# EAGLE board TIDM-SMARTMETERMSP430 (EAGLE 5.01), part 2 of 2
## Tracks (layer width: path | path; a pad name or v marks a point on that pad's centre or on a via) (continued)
N$16 (continued)
  Top 0.406: R21.2 57.91,46.72 58.14,46.49 57.91,46.27 R20.1
N$17
  Top 0.813: 2.2,61.68 U$2.3 | U$2.2 2.2,61.68 | 2.2,61.68 2.26,61.73
N$19
  Top 0.406: R22.2 57.91,50.84 57.88,50.81 57.91,50.79 R21.1 57.87,48.54 57.63,48.78 56.87,48.78 56.09,49.55 54.59,49.55 54.55,49.52 | 54.55,49.52 54.33,49.29 | R23.1 54.55,49.52
N$20
  Top 0.406: C26.1 R43.1
N$21
  Top 0.254: 119.92,66.11 119.86,66.05 | U4.2 119.92,66.11 | 119.92,66.11 119.95,66.14
  Top 0.406: 119.95,66.14 R51.2
N$22
  Top 0.254: 109.52,69 109.55,69.02 Q3.B 109.66,69.39 109.44,69.61
  Top 0.406: R52.2 108.34,71.98 109.44,70.88 109.44,69.61
N$23  (via drill 0.6)
  Top 0.406: R119.1 27.15,43.19 v28.42,43.95 | ISO1.1 22.76,53.28 22.83,53.35 23.08,53.1 v25.62,53.1
  Bottom 0.406: v28.42,43.95 28.42,50.3 v25.62,53.1
N$26
  Top 0.254: R50.2 110.69,67.04 | 114.78,67.47 114.75,67.45 | 114.78,67.47 114.8,67.45 | 113,68.95 113.99,69.94 | 113.25,67.45 113.25,67.58 | 114.78,67.47 114.78,67.58 114.72,67.52 U4.6
  Top 0.406: U4.6 113.25,67.45 111.09,67.45 110.69,67.04 | RS-232.2 129.05,68.64 127.99,67.58 122.63,67.58 121.13,69.84 113.99,69.94 | 113,68.95 113,67.83 113.25,67.58
N$27
  Top 0.406: R4.1 R54.2
N$28
  Top 0.406: R54.1 R55.2
N$29
  Top 0.406: R57.2 R55.1 68.64,44.55 68.59,44.5 | 68.59,44.5 68.55,44.46 | R56.1 68.59,44.5
N$30
  Top 0.254: LED3.C 98.02,118.11 98.01,118.12 R3.2
N$31
  Top 0.61: 104.68,31.29 104.69,31.31 | 104.68,31.29 R29.1 104.53,31.29 104.52,31.28 104.47,31.33 103.5,31.33 102.33,32.5 102.33,40.4 101.32,41.41 100.05,41.41 R101.2 | L7.2 104.67,31.28 104.68,31.29
N$32
  Top 0.61: R26.1 89.78,30.8 89.57,30.59 89.57,28.94 | L5.2 89.57,28.94 | 89.57,28.94 89.61,28.94 89.4,29.15 88.51,29.15 87.19,29.98 87.19,41.57 86.58,42.18 85.31,42.18 R104.2
N$33
  Top 0.61: L15.2 133.6,31.07 133.75,31.23 133.69,31.29 R62.1 132.57,31.29 132.07,31.53 132.07,41.39 131.24,42.23 R103.2
N$34
  Top 0.61: R63.1 119.6,31.51 119.62,31.49 L14.2 | R63.1 119.36,31.45 | 119.2,31.64 119.39,31.45 R63.1 | R63.1 119.41,31.45 119.35,31.51 118.33,31.51 117.37,32.98 117.37,41.11 116.2,42.28 R102.2
N$35
  Top 0.61: L16.2 107.72,31.15 107.74,31.18 107.64,31.28 R64.1 108.8,31.29 109.01,31.51 109.01,33.87 110.1,34.96 110.1,40.04 112.34,42.28 R102.1 112.49,42.94 116.81,47.26 JP10.2
N$36
  Top 0.61: 122.35,28.26 122.32,28.29 L17.2 | 122.35,28.26 R65.1 123.48,31.32 123.92,31.76 123.92,34.3 124.68,35.06 124.68,39.38 127.73,42.43 128.49,42.43 128.57,42.35 R103.1 128.7,42.38 130.53,44.21 JP11.2 | 122.35,28.26 122.4,28.21
N$37
  Top 0.254: TP4.TP 115.54,156.98 115.51,157.01 RF1.13
N$38
  Top 0.254: R66.1 101.24,150.3 102.84,151.9 104.87,151.9 104.85,151.93 RF1.6
N$39
  Top 0.254: R67.1 101.67,152.01 102.84,153.17 105.13,153.17 105.1,153.2 RF1.8
N$40
  Top 0.254: R68.1 102.2,153.81 102.84,154.44 104.36,154.44 104.39,154.47 RF1.10
N$41
  Top 0.406: 81.05,25.77 77.16,25.77 76.55,26.38 76.55,27.06 76.68,27.19 76.53,27.33 L6.1
  Top 0.61: X4.1A 82.37,13.11 82.39,13.09 82.37,13.07 | D3.A 81.73,34.35 81.81,34.28 81.73,34.2 D4.C 81.56,32.98 81.5,33.03 80.49,33.03 79.73,32.27 79.73,28.71 81.05,27.39 81.05,25.77 81.1,25.71 | TVS1.A 81.1,25.71 | 81.1,25.71 81.17,25.64
  Top 0.813: 81.16,25.5 TVS1.A
  Top 1.27: X4.1 82.37,13.07 | X4.1A 82.37,24.29 81.16,25.5
N$42
  Top 0.254: R69.1 103.2,155.56 103.35,155.71 104.36,155.71 104.39,155.74 RF1.12
N$43
  Top 0.61: X7.1A 122.07,13.1 122.07,13.09 | D23.A 126.39,33.11 D24.C 125.32,32.9 124.94,32.52 124.94,26.53 125.01,26.45 126.21,26.45 126.23,26.43 126.27,26.46 TVS4.A 126.21,26.43 | 123.87,23.63 123.92,23.63 123.92,23.89 | 125.95,23.63 126.21,23.89 | 122.32,25.49 L17.1
  Top 0.813: 123.92,23.89 122.32,25.49
  Top 1.27: X7.1 122.07,13.09 | X7.1A 122.07,21.84 123.87,23.63 | 123.92,23.63 125.95,23.63 | 126.21,23.89 126.21,26.43
N$45
  Top 0.254: R70.1 102.99,157.34 103.35,156.98 104.62,156.98 104.64,157.01 RF1.14
N$46
  Top 0.254: R71.1 102.28,159.07 103.09,158.25 104.36,158.25 104.39,158.28 RF1.16
N$47
  Top 0.61: X6.2A 113.82,13.21 113.84,13.22 | TVS3.C 115.48,26.51 115.41,26.58 115.42,26.58 116.81,26.58 | 116.81,26.58 L14.1 | 115.03,32.6 D18.C | 115.03,32.6 D17.A | 115.03,32.6 116.3,32.63 116.81,31.99 116.81,26.58 | TVS3.C 115.46,26.12 115.31,25.97 115.41,25.87 | TVS3.C 115.13,25.77 115.26,25.64 115.29,25.67
  Top 1.27: X6.2 X6.2A | 113.84,13.22 113.84,20.38 115.26,21.81 115.26,25.64
N$48
  Top 0.61: 96.13,25.87 96.03,25.87 | 96.13,25.87 TVS2.A | 96.13,25.87 96.13,25.77 96.06,25.84 94.84,25.84 94.84,25.87 94.81,32.35 95.14,32.78 D8.C 96.39,32.98 D7.A | X5.1A 95.64,13.13 95.68,13.09 95.64,13.06
  Top 0.813: 96.13,25.77 96.24,25.67 95.64,25.07 | L8.1 92.43,25.92 92.48,25.87 94.84,25.87
  Top 1.27: X5.1 95.64,13.06 | X5.1A 95.64,25.07
N$49
  Top 0.61: X6.1A 108.8,13.33 108.78,13.35 | TVS3.A 111.38,25.9 111.2,25.72 111.45,25.47 | 111.38,26.21 111.48,26.3 | TVS3.A 111.38,26.21 | 109.93,26.11 111.28,26.11 111.38,26.21 | L16.1 109.77,26.11 109.93,26.11 | 111.48,32.55 D20.C | 111.48,32.55 D19.A | 111.48,32.55 110.15,32.5 109.93,32.07 109.93,26.11 | TVS3.A 111.38,25.95 111.17,25.74 | 111.48,26.12 111.53,26.17 | 111.48,26.12 TVS3.A | 111.27,25.92 111.48,26.12
  Top 1.27: X6.1 X6.1A | 108.8,13.33 108.8,17.97 111.27,20.43 111.27,25.92
N$50
  Top 0.254: R72.1 101.65,160.82 102.99,159.47 104.57,159.47 104.64,159.55 RF1.18
N$51
  Top 0.254: R73.1 101.26,162.65 103.07,160.85 104.74,160.85 RF1.20 104.85,160.74
N$52
  Top 0.254: 47.21,150.66 RF3.3 46.93,150.66 46.96,150.63 49.25,150.63 50.19,149.69 54.5,149.69 54.58,149.62 54.62,149.66 R108.2
N$53
  Top 0.254: RF1.15 TP13.TP
N$54
  Top 0.254: TP10.TP 115.31,159.55 115.29,159.52 115.26,159.55 RF1.17
N$55  (via drill 0.9)
  Top 0.813: U$2.8 14.39,56.46 14.45,56.4 v14.45,53.61
  Bottom 0.813: C59.1 11.15,6.62
  Bottom 1.27: v14.45,53.61 16.48,51.57 16.48,11.95 11.15,6.62
N$56
  Top 0.254: RF3.6 41.65,151.93 39.34,149.62 R77.1
N$57
  Top 0.254: RF3.8 40.89,153.2 39.09,151.4 38.07,151.4 37.99,151.47 R78.1
N$58
  Top 0.254: RF3.10 40.13,154.47 39.09,153.43 38.07,153.43 37.97,153.33 R79.1
N$59
  Top 0.254: RF2.18 74.62,159.55 74.65,159.52 74.58,159.46 R74.2
N$60
  Top 0.254: RF3.12 39.36,155.74 38.83,155.21 38.07,155.21 37.99,155.13 R80.1
N$61
  Top 0.254: R81.1 38.22,157.09 38.32,156.98 38.35,157.01 RF3.14
N$62
  Top 0.254: RF3.16 39.57,158.28 39.09,158.76 38.07,158.76 37.99,158.84 R82.1
N$63
  Top 0.254: RF3.18 40.1,159.55 39.06,160.59 38.12,160.59 38.07,160.54 37.97,160.64 R83.1
N$64
  Top 0.254: RF3.20 40.58,160.82 39.09,162.32 38.07,162.32 37.98,162.41 R84.1
N$65
  Top 0.254: R85.2 9.84,159.56 9.88,159.52 9.9,159.55 RF4.18
N$66
  Top 0.254: R87.1 18.77,158.25 18.74,158.28 RF4.15
N$67
  Top 0.254: RF3.11 52.78,155.74 TP25.TP
N$68
  Top 0.254: RF3.13 50.49,157.01 TP24.TP
N$69
  Top 0.254: TP27.TP 53.06,158.25 53.03,158.28 RF3.15
N$71
  Top 0.254: TP26.TP 50.54,159.55 50.52,159.52 50.49,159.55 RF3.17
N$72
  Top 0.61: 131.64,26.9 130.92,26.9 130.5,26.48 TVS4.C 130.3,26.4 130.4,26.3 | 131.64,26.9 L15.1 | 129.59,32.88 D22.C | 129.59,32.88 D21.A | 129.59,32.88 130.68,32.88 131.03,32.52 131.03,28.71 131.54,28.21 131.54,27.19 131.64,27.09 131.64,26.9
  Top 1.27: X7.2 X7.2A 127.09,22.34 128.09,23.33 129.76,23.33 130.4,23.96 130.4,26.3
N$73  (via drill 0.5)
  Top 0.254: Q1.B 20.21,44.63 v19.27,43.7 | R120.2 19.36,50.9 19.27,50.81 v19.27,49.03
  Top 0.406: Q1.B 20.61,44.53 20.54,44.46 20.54,43.19 19.53,42.18 19.53,40.4 | R112.1 17.15,39.8 17.75,40.4 19.53,40.4 | 19.53,40.4 D10.C
  Bottom 0.254: v19.27,43.7 v19.27,49.03
N$74
  Top 0.61: 42.73,125.83 42.64,125.74 | 42.73,125.83 R9.1 | 42.73,125.83 45.09,125.83 47.47,123.46 47.47,121.17 47.44,121.15 U$7.4
N$75
  Top 0.254: R10.2 72.87,150.38 73.12,150.63 73.88,150.63 73.91,150.66 RF2.4
N$76
  Top 0.254: R88.2 118.33,92.72 OK1.2
N$77  (via drill 0.5)
  Top 0.254: 116.05,58.43 116.07,58.41 C32.-
  Top 0.406: D16.A 119.63,58.15 119.6,58.18 C32.- | U4.5 116.43,68.72 116.81,68.34 116.81,63.51 v118.1,62.67 | v118.08,59.96 116.56,59.96 116.05,59.45 116.05,58.43
  Bottom 0.406: v118.08,59.96 v118.1,62.67
N$78  (via drill 0.6)
  Top 0.406: R45.1 124.6,69.52 126.46,71.39 RS-232.3 | v126.72,59.96 124.94,58.18 124.91,58.15 D16.C
  Bottom 0.254: v126.72,59.96 126.72,60.21 | 132.56,71.39 RS-232.3
  Bottom 0.406: 126.72,60.21 131.29,64.78 131.29,70.12 132.56,71.39
N$79  (via drill 0.6)
  Top 0.254: 119.86,67.58 119.92,67.52 U4.3 | 113.65,71.5 v113.76,71.39
  Top 0.406: v117.83,67.58 119.86,67.58 | Q3.C 113.65,71.5
  Bottom 0.406: v113.76,71.39 115.03,71.39 117.83,68.59 v117.83,67.58
N$80
  Top 0.254: OK1.4 126.72,99.83 SL1.1
N$81
  Top 0.406: SL1.2 121.89,98.31 OK1.3
N$82
  Top 0.254: RF1.5 111.96,151.93 112.75,151.14 R27.2 114.52,151.14
N$84
  Top 0.254: OK2.2 109.7,116.6 111.73,114.57 111.73,113.04 R89.2
N$85
  Top 0.254: R40.2 72.87,152.16 73.12,151.9 73.88,151.9 73.91,151.93 RF2.6
N$86
  Top 0.254: OK2.4 SL2.1
N$87
  Top 0.254: OK2.3 SL2.2
N$88
  Top 0.406: R111.2 R110.1
N$89
  Top 0.406: R41.1 79.76,153.21 79.73,153.17 79.7,153.2 RF2.7
N$91
  GND 0: 75.41,74.69 75.41,76.21 71.85,79.77 71.85,91.96 72.11,92.21 76.68,92.21 76.93,91.96 76.93,76.97 76.68,76.72 76.68,74.69
N$93  (via drill 0.5)
  Top 0.406: ISO1.2 22.3,50.54 | ISO1.2 24.63,50.54 26.89,48.27 26.89,46.49 26.73,46.66 C30.1 | D10.A 23.01,41.49 v22.32,42.18 | 22.58,50.56 22.32,50.81 v22.32,48.53 | 22.58,50.56 22.6,50.54 ISO1.2 | 22.58,50.56 22.66,50.64 22.66,51.24 21.05,52.84 18.26,52.84 17.66,52.25 R120.1 17.66,48.14 17.5,47.98 D25.A
  Bottom 0.406: v22.32,42.18 v22.32,48.53
N$94
  Top 0.406: R126.1 14.36,89.84 14.13,89.61 Q5.1 14.13,89.49 14.19,89.42 14.13,89.36 14.13,88.61 15.21,87.53 15.21,85.61 14.84,85.24 Q4.1
N$97
  Top 0.406: Q5.2 12.3,89.55 12.23,89.49 Q4.2
N$98
  Top 0.406: R36.1 22.32,101.1 22.32,99.83 22.58,99.58 23.59,99.58 24.21,98.96 24.21,97.91 Q9.1 | Q9.1 | Q8.1 Q9.1
N$99
  Top 0.406: R117.1 23.5,68.76 23.34,68.59 23.08,68.85 R118.2
N$100
  VCC 0: 75.41,74.69 75.41,76.21 71.85,79.77 71.85,91.96 72.11,92.21 76.68,92.21 76.93,91.96 76.93,76.97 76.68,76.72 76.68,74.69
N$103
  Top 0.406: 27.57,69.01 27.66,69.1 | 27.57,69.01 R116.1 | R117.2 27.4,68.85 27.57,69.01
N$104
  Top 0.254: RF1.3 111.7,150.66 113,149.36 R61.2 114.52,149.36
N$105
  Top 0.254: RF1.9 113.02,154.47 113.25,154.7 114.27,154.7 114.29,154.72 R60.2
N$106
  Top 0.254: R76.1 80.5,158.27 80.49,158.25 80.46,158.28 RF2.15
N$107
  Top 0.254: R75.1 82.81,160.76 82.75,160.82 RF2.19
N$108
  Top 0.254: R86.1 21.08,160.82 21.05,160.79 21.03,160.82 RF4.19
N$109
  Top 0.254: R107.2 48.79,154.75 48.48,154.44 46.45,154.44 46.48,154.47 RF3.9
N$110
  Top 0.254: R105.2 54.58,151.4 | R105.2 | R105.2 | R105.2 49.69,151.46 49.25,151.9 46.96,151.9 46.71,152.16 46.55,152.01 RF3.5
N$111
  Top 0.254: RF3.7 46.68,153.2 46.71,153.17 R106.2
N$113
  Top 0.406: R119.2 23.08,43.19 22.32,43.95 22.32,44.46 22.51,44.65 | 22.51,44.65 22.58,44.72 | Q1.E 22.51,44.65
N$115
  Top 0.61: R8.1 20.04,133.62 19.78,133.36 17.39,133.36 14.78,130.75 14.78,128.87 14.7,128.79 14.73,128.77 U$5.4
N$117
  Top 0.406: R121.2 26.89,59.96 26.81,59.87 Q2.E
N$118
  Top 0.406: R121.1 34.26,59.96 35.28,60.97 35.28,65.29 35.44,65.45 IS02.1 35.46,65.72 35.53,65.8
N$120
  Top 0.406: R123.2 27.4,71.39 27.32,71.3 Q6.E
N$121
  Top 0.406: 33.24,71.89 33.23,71.91 ISO3.1 33,71.91 32.99,71.89 29.18,71.89 28.76,71.47 R123.1
N$125
  Top 0.406: R111.1 21.05,37.86 20.8,37.6 20.54,37.86 R112.2
N$128  (via drill 0.5)
  Top 0.254: U$10.P$12 15.69,96.25 15.21,95.77 v15.21,95.26
  Top 0.406: 741G57.4 18.48,81.83 18,82.05 v16.99,82.05
  Bottom 0.254: v15.21,95.26 15.21,93.23 15.72,92.72
  Bottom 0.406: 15.72,92.72 18.77,92.72 19.53,91.96 19.51,87.93 16.99,86.63 v16.99,82.05
N$129
  Top 0.406: 10.13,82.05 10.38,81.8 10.38,80.53 10.34,80.58 BZ1.P$1 10.31,72.33 8.61,70.62 8.61,46.24 4.03,43.19 2.76,43.19 2.51,43.45 2.32,43.25 U$1.1 2.45,43.25 2.51,43.19 PLCV1.1 | 10.13,82.05 8.95,83.24 R33.2 8.86,84.59 | Q4.3 11.01,82.94 10.13,82.05
N$130
  Top 0.406: R114.2 R113.1
N$131
  Top 0.406: Q9.2 22.31,98.07 22.32,98.06 22.31,98.05 Q8.2
N$132  (via drill 0.5)
  Top 0.254: R47.1 110.56,73.06 110.84,72.78
  Top 0.406: 110.84,72.78 112.9,72.81 U3.8 115.92,72.78 117.06,73.93 117.06,80.02 J3.1 | R51.1 124.85,64.44 v125.95,65.54
  Bottom 0.406: J3.1 124.94,82.56 125.95,81.55 v125.95,65.54
N$139
  Top 0.406: Q11.1 35.51,99.57 35.53,99.58 35.51,99.6 Q10.1 35.51,101.63 34.21,102.63 20.31,102.63 19.27,101.87 19.27,100.6 19.36,100.68 R37.1
N$140
  Top 0.406: Q10.2 33.61,99.44 33.5,99.33 33.61,99.21 Q11.2
N$143
  Top 0.406: R115.2 R114.1
N$144  (via drill 0.5)
  Top 0.406: 21.81,59.7 21.64,59.87 Q2.B 21.63,58.75 21.05,58.18 18.42,58.18 18.17,57.92 18.17,57 18.26,56.91 | v24.35,65.8 D11.C | 18.26,56.91 R115.1 | v17.75,54.37 17.75,56.4 18.26,56.91 | v34.26,70.12 34.31,70.12 35.12,69.3 35.12,68.19 35.02,68.08 R122.2
  Bottom 0.406: v17.75,54.37 16.73,55.38 16.73,64.02 18.51,65.8 v24.35,65.8 24.35,67.83 26.13,69.61 33.75,69.61 v34.26,70.12
N$145  (via drill 0.5)
  Top 0.406: Q6.B 22.13,71.2 21.89,70.96 20.37,70.96 19.02,69.61 19.02,68.59 | 19.02,68.59 18.93,68.68 R118.1 | D9.C 28.42,77.99 v30.2,79.26 | 19.02,68.59 19.02,68.34 18.77,68.34 v17.5,67.07
  Top 0.61: D9.C 29.69,77.99 30.7,76.97 R124.2 30.7,75.2
  Bottom 0.406: v30.2,79.26 25.62,79.26 19.02,72.66 19.02,68.59 v17.5,67.07
N$202
  Top 0.406: R28.1 76.46,31.8 76.42,31.76 76.53,31.65 L6.2
  Top 0.61: R28.1 77.78,31.8 79.07,33.34 79.07,38.6 81.63,40.91 81.61,40.93 R104.1 82.37,41.01 85.06,43.7 87.85,43.7 90.65,46.49 JP3.2
N$229
  Top 0.61: L8.2 92.43,31 92.45,31.03 R31.1 93.48,31.29 93.95,31.76 93.95,34.56 94.89,35.5 94.89,39.31 97.35,41.01 R101.1 | JP4.2 103.09,45.99 101.06,43.95 98.57,43.95 97.4,42.79 R101.1 | R101.1 97.38,40.98
OPTO  (via drill 0.5)
  Top 0.254: R88.1 118.33,88.66 118.59,88.4 JP5.1 123.34,85.94 v123.34,79.64 | v79.98,67.32 79.98,61.99 80.49,61.48 v81.22,61.48 | MSP430F47187.68 74.8,73.52 v76.17,72.15
  Bottom 0.254: 123.41,79.51 123.34,79.59 v123.34,79.64 | v76.17,72.15 76.17,71.89 79.98,68.08 v79.98,67.32 | 120.37,59.96 117.57,57.16 104.36,57.16 100.05,61.48 v81.22,61.48
  Bottom 0.406: 120.37,59.96 120.37,76.47 123.41,79.51
OPTO2  (via drill 0.5)
  Top 0.254: MSP430F47187.46 84.15,71.6 83.69,70.63 83.79,67.32 83.68,67.22 v83.68,67.16 | JP6.1 117.57,113.04 R89.1 | R89.1 113.25,113.04 | R89.1 113.7,112.98 113.51,112.79 113.74,112.56 113.74,104.38 v113.25,103.9
  Bottom 0.254: 121.61,108.98 JP6.1 121.64,108.72 | v83.68,67.16 83.7,67.16 83.79,67.07 83.84,67.12 85.42,67.12 88.13,64.43 101.21,64.43 102.33,65.54 102.33,83.32 104.36,85.36 109.24,85.36 110,86.11 110,86.12 113.76,89.93 113.76,103.39 v113.25,103.9
P1+
  Top 0.406: X1.2A
  Top 0.813: L1.1 44.66,23.9 44.93,23.63 44.66,23.36
  Top 1.27: X1.2 X1.2A 44.66,23.36
P1+1  (via drill 0.9)
  Top 0.406: R110.2 26.98,37.77 27.15,37.6 26.89,37.35
  Top 0.813: R12.2 38.39,33.22 44.42,27.19 44.33,27.1 R17.2 44.18,26.95 | 42.9,23.89 42.96,23.95 L1.2 | U$6.18 7.08,122.69 1.49,117.11 1.49,81.8 v2.26,81.04 | v6.57,47.76 v6.57,59.19 | v5.05,22.36 18.77,22.36 25.19,28.79 C58.2 25.19,33.36 26.89,35.06 26.89,37.6 26.98,37.69 R110.2 | U$4.L 28.42,37.6 27.15,37.6
  Top 1.27: 44.18,26.95 42.9,25.67 42.9,23.89
  Bottom 0.61: 25.12,28.71 25.19,28.79 C58.2 | 27.15,26.68 27.4,26.68
  Bottom 0.813: R17.2 44.08,27.36 43.4,26.68 | v2.26,81.04 2.26,69.1 0.99,67.83 0.99,64.78 v6.57,59.19
  Bottom 1.27: 27.4,26.68 43.4,26.68 | 25.12,28.71 27.15,26.68 | v6.57,47.76 6.57,41.92 5.05,40.4 v5.05,22.36
P1-
  Top 0.813: X1.1A 39.64,13.01 39.59,12.97 39.64,12.92 | 38.58,23.63 38.59,23.65 L2.1
  Top 1.27: X1.1 39.64,12.92 | X1.1A 39.64,21.56 38.58,22.62 38.58,23.63
P1-1  (via drill 0.9)
  Top 0.406: JP1.2 32.25,44.74 32.23,44.72 32,44.95 | 38.3,44.95 38.27,44.92 R16.2 | JP1.2 38.3,44.95 | 38.3,44.95 38.32,44.97 | JP1.2 32.46,44.95 32.48,44.97 34.51,42.94 34.51,40.14 32.22,37.85 32.23,37.6 R18.2 | 14.3,76.61 14.19,76.72 | U$3.5 14.3,76.61 | 14.3,76.61 14.45,76.47 | C50.2 23.08,63.51 22.58,63 Q2.C | Q2.C 22.58,61.99 | C53.2 26.04,74.52 26.13,74.43 26.13,73.93 25.71,73.5 Q6.C 22.91,73.5 22.83,73.42 21.81,73.42 20.37,71.97 D27.C 19.02,71.89 18,71.89 17.5,72.4 16.73,72.4 | Q2.C 22.41,62.07 22.32,61.99 20.04,61.99 18.51,60.46 D26.C 16.91,59.78 16.73,59.96 16.73,63.51 16.23,64.02 14.45,64.02 14.39,64.08 U$2.5 | 32,44.95 31.97,44.97 26.13,44.97 25.03,46.07 C30.2 24.86,46.75 24.78,46.83 Q1.C 18.85,46.83 17.5,45.48 D25.C 17.5,44.46 17.37,44.59 16.49,44.59 16.09,45.01 16.09,50.7 15.97,50.81 14.19,50.81 | JP1.2 32,44.95 | R46.2 3.53,106.18 4.54,105.17 7.08,105.17 U$6.1
  Top 0.61: U$2.5 14.51,64.08 14.7,64.27 14.7,66.05 16.73,68.08 16.73,72.4 16.73,75.96 16.48,76.21 14.45,76.21 14.39,76.27 U$3.5
  Top 0.813: 33.88,31.38 32.2,33.06 32.23,35.57 R18.2 | 33.88,31.38 34.02,31.24 | 33.88,31.38 34.01,31.51 34.02,31.5 R17.1 34.02,25.65 35.53,24.14 36.8,24.14 36.88,24.07 L2.2 36.89,23.98 36.8,23.89 | 14.19,76.72 14.19,78.24 v13.18,79.26 | U$2.5 14.25,64.08 14.19,64.02 11.4,64.02 10.64,63.26 10.64,51.32 11.15,50.81 14.19,50.81 14.25,50.87 U$1.5
  Top 1.27: v12.42,14.49 34.51,14.49 36.8,16.78 36.8,23.89
  Bottom 0.813: 6.96,38.99 U$4.N | v13.18,79.26 9.62,79.26 7.84,81.04 7.84,104.66 U$6.1
  Bottom 1.27: v12.42,14.49 9.37,14.49 7.84,16.01 7.84,38.11 6.96,38.99
P1.5  (via drill 0.5)
  Top 0.254: v57.63,73.67 v55.6,73.67 | v68.1,68.5 68.2,68.5 68.3,68.6 MSP430F47187.86
  Top 0.406: PLC_GPIO.1 46.45,91.2 v47.98,89.93
  Bottom 0.254: v55.6,73.67 55.6,80.78 48.99,87.39 | v68.1,68.5 61.25,68.49 60.42,67.58 57.88,67.58 57.12,68.34 57.12,73.16 v57.63,73.67 | 48.99,87.39 48.97,87.41 | v47.98,89.93 47.98,88.4 48.99,87.39
P2+
  Top 0.813: X2.2A 58.54,13.07 58.64,12.97 58.54,12.86
  Top 1.27: X2.2 58.54,12.86 | L3.1 57.66,24.36 58.54,23.48 X2.2A
P2+1  (via drill 0.7, 0.9)
  Top 0.406: R24.2 55.79,33.48 | 55.85,33.29 55.8,33.24 R24.2 | R24.2 55.79,33.22
  Top 0.61: R113.2 28.51,48.18 v29.69,47
  Top 0.813: R19.2 57.96,35.65 55.79,33.48 | 33.24,17.79 C60.2 | 56.06,33.24 56.1,33.29 | R24.2 56.06,33.24 | L3.2 55.96,33.15 56.06,33.24
  Top 1.27: v30.45,29.48 30.45,20.59 33.24,17.79
  Bottom 0.813: 55.8,33.24 55.6,33.03 | C60.2 33.24,17.79 | v30.45,29.48 30.45,31.25 27.91,33.79 27.66,39.13 29.69,42.18 29.69,46.49 29.94,46.75 v29.69,47 | 55.85,33.29 55.8,33.24 | 55.8,33.24 R24.2
  Bottom 1.27: C60.2 52.8,17.79 55.85,20.84 55.85,33.29
P2-
  Top 0.406: X2.1A 53.52,13.01 53.56,12.97 53.52,12.92 | 49.5,24.14 49.41,24.23 | 49.5,23.89 49.46,23.93
  Top 0.813: 49.46,24.1 49.5,24.14
  Top 1.27: X2.1 53.52,12.92 | 49.41,24.23 L4.1 | X2.1A 53.52,19.11 49.5,23.13 49.5,23.89 | 49.46,23.93 49.46,24.1
P2-1
  Top 0.406: 51.02,42.18 51.05,42.2 R25.2 | JP2.2 49.22,49.52 49.25,49.54 49.27,49.52 51.79,49.52 | 51.79,49.52 R23.2 | 51.79,49.52 51.79,49.54 51.28,49.03 51.28,42.68 51.16,42.57 R25.2 | 45.63,36.78 R24.1 45.63,36.4 | 51.28,42.18 51.25,42.2 R25.2
  Top 0.813: 45.63,36.78 51.28,40.14 51.28,42.18 | L4.2 51.11,30.91 45.63,36.4
P2.0  (via drill 0.5)
  Top 0.254: MSP430F47187.83 72.38,70.1 74.39,68.08 75.41,68.08 75.46,68.13 v75.59,68.13
  Bottom 0.254: v75.59,68.13 75.61,68.13 75.66,68.08 74.65,67.07 62.45,67.07 60.68,65.29 57.88,65.29 56.61,66.56 56.61,77.99 61.18,82.56 63.98,82.56 65.5,84.09 65.5,88.91 66.52,89.93 66.52,113.04 63.72,115.84 63.72,123.96 64.99,125.23 RF2_FIFO.3
P2.6  (via drill 0.5)
  Top 0.254: MSP430F47187.77 70.4,73.1 70.58,72.91 70.58,72.4 70.84,72.15 72.36,72.15 72.54,72.33 72.54,74 72.36,74.18 70.84,74.18 70.58,74.43 70.58,75.2 69.36,76.42 v69.16,76.42 | v82.27,145.81 82.77,145.3 94.97,145.3 99.28,141.24 100.05,140.47 130.53,140.47 RF1_FIFO.3 | v69.82,147.33 70.33,147.33 74.14,143.52 79.22,143.52 82.01,140.73 v81.76,140.73
  Bottom 0.254: v69.16,76.42 67.53,78.24 67.53,87.9 68.52,88.91 68.55,102.07 68.55,102.53 70.89,105.12 70.89,146.77 v69.82,147.33 | v82.27,145.81 82.27,141.24 v81.76,140.73
P2.7  (via drill 0.5)
  Top 0.254: MSP430F47187.76 71.17,73.6 v71.62,73.01 | PLC_GPIO.3 48.99,96.79 52.55,93.23 v52.8,93.23 | v64.74,80.28 v64.74,93.23
  Bottom 0.254: v71.62,73.01 63.88,73.01 63.47,73.42 63.47,79.01 v64.74,80.28 | v64.74,93.23 v52.8,93.23
P3+
  Top 0.406: 73.53,13.37 73.63,13.47
  Top 1.27: X3.2 X3.2A 73.53,13.37 | 73.63,13.47 73.63,19.65 70.89,22.39 70.89,24.6 70.84,24.65 70.87,24.69 L12.1
P3+1  (via drill 0.7)
  Top 0.406: 69.24,28.13 R59.2 69.24,28.03 69.31,27.95 69.17,27.81
  Top 0.61: R116.2 29.94,68.85 30.45,68.34 v30.45,65.54
  Top 0.813: R4.2 71.34,30.24 69.24,28.13 | 69.17,27.81 L12.2
  Bottom 0.813: 69.24,28.03 R59.2 | v30.45,65.54 30.2,65.8 29.94,65.54 | 33.24,6.87 C59.2 33.32,6.79
  Bottom 1.27: 69.24,28.03 70.84,26.43 70.84,6.62 69.31,5.09 35.02,5.09 33.32,6.79 | 29.94,65.54 27.91,65.54 24.1,61.73 24.1,51.57 26.39,49.29 26.39,35.83 23.08,32.52 23.08,17.03 33.24,6.87
P3-
  Top 0.406: X3.1A 68.51,13.01 68.55,12.97 68.51,12.92 | L13.1 64.25,24.66 64.23,24.65 64.44,24.44 | 64.23,24.4 64.25,24.41
  Top 1.27: X3.1 68.51,12.92 | X3.1A 68.51,19.11 64.23,23.38 64.23,24.4 | 64.25,24.41 L13.1
P3-1
  Top 0.406: 66.01,24.9 65.95,24.84 L13.2 | R56.2 65.37,44.59 63.47,42.68 63.37,42.79 JP9.2 63.57,42.84 65.5,40.91 65.5,38.37 64.91,37.77 R58.2 64.91,35.91 64.99,35.83 | 61.03,31.4 61.33,31.4
  Top 0.813: 61.33,31.4 64.74,34.81 64.74,35.57 64.99,35.83
  Top 1.27: R59.1 61.03,31.4 66.01,26.43 66.01,24.9
P4.0  (via drill 0.5)
  Top 0.254: 81.78,75.3 81.8,75.31 MSP430F47187.54 81.8,74.58 79.98,72.79 79.98,72.54 79.98,68.59 80.34,68.24 81.66,68.24 82.01,68.59 | 82.01,68.59 | 82.01,68.59 v81.93,68.59
  Bottom 0.254: v81.93,68.59 82.01,68.59 82.52,68.08 85.31,68.08 88.39,64.99 100.97,64.99 101.82,65.86 101.82,83.58 104.11,85.86 109,85.86 109.38,86.25 109.39,86.25 113.25,90.11 113.25,101.61 111.98,102.88 111.98,123.71 116.43,128.16 RF1_GPIO.1
P4.4  (via drill 0.5)
  Top 0.254: MSP430F47187.50 85.75,73.6 86.84,74.43 86.84,78.75 v87.09,79.26 | v88.11,115.84 83.79,115.84 78.46,121.17 v73.88,121.17 | 6.32,136.66 6.5,136.84 RF2_GPIO.3 6.57,136.92 10.89,141.24 v73.88,141.24
  Bottom 0.254: v87.09,79.26 88.36,79.26 92.17,82.82 92.17,87.13 94.22,89.17 94.22,91.21 87.09,98.31 87.08,114.82 | 87.08,114.82 v88.11,115.84 87.09,114.82 87.08,114.82 | v73.88,141.24 v73.88,121.17 | RF2_GPIO.3 6.57,136.66
P5.0  (via drill 0.5)
  Top 0.254: MSP430F47187.55 81.3,76.26 83.28,78.24 v84.3,78.24 | RF1_GPIO.3 118.97,129.43 119.1,129.3 115.29,125.49 v100.55,125.49
  Bottom 0.254: v84.3,78.24 90.9,78.24 92.93,80.28 92.93,86.63 94.7,88.4 94.71,105.17 89.38,110.5 89.38,114.57 v100.55,125.49
P5.6  (via drill 0.5)
  Top 0.254: MSP430F47187.61 78.3,76.56 78.71,76.97 78.71,78.5 v79.22,79.01 | RF2_FIFO.1 62.45,125.23 63.72,126.5 v80.74,126.5
  Bottom 0.254: v79.22,79.01 79.22,87.13 76.68,89.67 76.68,92.72 79.73,95.77 79.73,109.23 77.95,111.01 77.95,114.06 79.73,115.84 79.73,125.49 v80.74,126.5
P5.7  (via drill 0.5)
  Top 0.254: MSP430F47187.62 77.8,67.47 v78.96,66.31
  Bottom 0.254: v78.96,66.31 85.31,66.31 85.33,66.32 87.88,63.82 101.37,63.82 102.84,65.29 102.84,83.07 104.62,84.85 109.44,84.85 114.27,89.67 114.27,111.77 116.81,114.31 130.27,114.31 132.05,116.09 RF1_FIFO.1
PC_GND  (via drill 0.5)
  Top 0.254: 123.16,76.21 D14.A | 132.63,76.9 132.66,76.87 RS-232.5 | 112.64,58.13 112.69,58.18 | 112.64,58.13 112.64,58.43 112.49,58.43 112.75,58.18 C32.+ | 112.64,58.13 112.62,58.1 | C31.- 112.49,61.73 112.64,61.89
  Top 0.406: 123.16,76.21 122.91,75.96 121.89,75.96 121.25,75.32 U3.3 118.46,75.32 118.08,75.7 v118.08,77.74 | D14.A 124.35,76.39 | v113.25,63.77 112.64,62.9 112.64,61.89 | 112.64,58.43 C31.-
  Top 0.61: 124.35,76.39 125.95,77.99 131.54,77.99 132.63,76.9 | RS-232.5 133.07,77.23
  Top 0.813: 131.54,77.99 131.29,78.24
  Top 1.27: 131.29,78.24 RS-232.G1
  Bottom 0.254: 118.59,77.74 v118.08,77.74
  Bottom 0.406: v113.25,63.77 118.59,63.77 119.35,64.27 119.35,76.97 118.59,77.74
PC_VCC
  Top 0.254: 132.81,74.18 132.76,74.13 RS-232.4 | 123.41,61.73 123.39,61.76 D15.A
  Top 0.406: 132.81,74.18 134.34,72.66 134.34,64.53 132.3,62.5 125.19,62.5 124.43,61.73 122.91,61.73 122.93,61.76 D15.A
PIN8
  Top 0.254: R50.1 110.69,65.06 110.84,64.91 | 119.6,61.73 119.63,61.76 D15.C | 114.78,65.04 114.72,64.98 U4.8
  Top 0.406: 110.84,64.91 U4.8 | 119.6,61.73 C31.+ 115.89,62.9 114.78,64.02 114.78,65.04
PLC_EN  (via drill 0.5)
  Top 0.254: JP7.2 JP7.4 JP7.6
  Top 0.406: U$14.9 49.93,99.76 v50.01,99.58
  Bottom 0.254: JP7.6 53.56,118.12 53.06,117.61 51.02,117.61 50.01,118.63 40.61,118.63 39.85,117.87 39.85,115.07 42.13,112.79 42.13,107.71 41.12,106.69 41.12,101.1 42.64,99.58 45.18,99.58 45.44,99.33 45.44,99.58
  Bottom 0.406: 45.18,99.58 45.44,99.58 v50.01,99.58
PLC_GPIO1
  Top 0.406: U$14.17 51.61,104.84 50.52,105.93 47.72,105.93 PLC_GPIO.2
PLC_GPIO2  (via drill 0.5)
  Top 0.406: U$14.30 59.99,112.46 v60.17,112.28
  Bottom 0.406: PLC_GPIO.4 57.63,104.66 60.17,107.2 v60.17,112.28
PLC_RESET  (via drill 0.5)
  Top 0.254: R109.1 49.08,112.45 49.25,112.28 49.42,112.46 U$14.29
  Top 0.406: 49.58,112.46 49.5,112.53 R109.1 49.08,112.7 48.99,112.79 v48.99,114.82
  Bottom 0.406: S4.1 58.14,119.9 55.09,116.85 50.26,116.85 48.99,115.58 v48.99,114.82
PLC_RX  (via drill 0.5)
  Top 0.254: U$14.12 62.28,101.03 v62.35,100.85 | v78.46,107.45 78.46,117.87 76.17,120.15 68.55,120.15 67.03,121.68 65.25,121.68 PLC_UART.4 | v78.71,96.53 78.71,95.26 81.5,92.47 113.76,92.47 v115.29,93.99 | v64.99,100.85 65.25,100.85 67.53,103.14 v67.53,106.18
  Top 0.406: U$8.3 39.66,136.09 v40.1,135.65 | v56.61,123.2 59.41,123.2 59.91,122.69 63.72,122.69 PLC_UART.4
  Bottom 0.254: PLC_UART.4 66.26,121.42 67.79,119.9 67.79,106.69 v67.53,106.18 | v62.35,100.85 v64.99,100.85 | v78.46,107.45 78.46,96.79 v78.71,96.53 | 109.95,84.09 114.78,88.91 114.78,93.48 v115.29,93.99
  Bottom 0.406: v40.1,135.65 40.1,129.81 46.71,123.2 v56.61,123.2 | JP13.2 106.9,62.24 108.68,64.02 108.68,82.82 109.95,84.09
PLC_TX  (via drill 0.5)
  Top 0.254: U$14.11 55.52,101.03 56.1,101.61 v56.1,115.84 | v115.67,91.71 81.5,91.71 v77.69,95.52 | v77.44,106.18 77.44,117.61 76.17,118.88 68.55,118.88 67.28,120.15 63.47,120.15 62.45,121.17
  Top 0.406: U$9.3 51.85,137.11 54.07,134.89 | 54.07,134.89 54.33,134.63 | PLC_UART.2 62.45,121.17 56.61,121.17 55.09,122.69 55.09,133.87 54.07,134.89 | v110.21,79.77 JP12.2
  Bottom 0.254: PLC_UART.2 61.69,121.42 v56.1,115.84 | 110.46,83.32 115.64,88.63 v115.67,91.71 | v77.69,95.52 77.69,105.93 v77.44,106.18
  Bottom 0.406: 110.46,83.32 110.46,80.02 v110.21,79.77
R33
  Top 0.254: C11.+ 88.11,80.53 87.07,81.52 81.86,81.52 80.49,80.1 78.53,80.15 78.2,79.46 78.2,77.23 77.3,76.32 MSP430F47187.63
RESETCC_A  (via drill 0.5)
  Top 0.254: MSP430F47187.47 87.55,72.1 89.38,73.93 89.38,80.02 87.35,82.05 83.03,82.05 v82.68,82.59 | R76.2 84.46,156.57 v84.55,156.48 | v117.83,150.63 117.83,150.38 117.06,151.14 R27.1
  Bottom 0.254: 83.28,126 86.58,129.3 86.58,154.44 v84.55,156.48 90.39,162.32 99.79,162.32 111.48,150.63 v117.83,150.63 | 83.28,126 82.52,125.23 | v82.68,82.59 82.24,82.59 81.53,83.3 81.53,89.37 81.5,111.43 81.5,111.77 81.76,112.03 81.76,124.47 83.28,126
RESETCC_B  (via drill 0.5)
  Top 0.254: v81.44,72.26 81.44,72.34 82.2,73.1 MSP430F47187.49 | R105.1 64.16,151.47 v64.23,151.4
  Top 0.406: R87.2 20.76,156.44 24.35,160.03 24.35,164.1 26.64,166.38 60.68,166.38 64.23,162.83 v64.23,151.4
  Bottom 0.254: v81.44,72.26 81.39,72.26 79.22,74.43 69.06,74.43 66.52,76.97 66.52,88.4 67.51,89.4 67.51,103.03 69.9,105.45 69.87,143.47 64.23,149.11 v64.23,151.4 64.49,151.14
RF1_GPIO1  (via drill 0.5)
  Top 0.254: R75.2 82.99,159.06 83.03,159.02 83.79,159.02 85.31,160.54 v90.9,160.54 | RF1_GPIO.2 116.43,131.97 116.56,131.84 115.29,130.57 v94.46,130.57
  Bottom 0.254: v90.9,160.54 90.9,134.12 v94.46,130.57
RF1_GPIO2  (via drill 0.5)
  Top 0.254: v70.58,148.86 70.58,148.09 74.39,144.28 94.97,144.28 98.52,140.98 98.52,140.73 105.38,133.87 117.32,133.87 119.1,132.09 119.07,132.07 RF1_GPIO.4
  Top 0.406: R74.1 70.68,156.32 v70.58,156.22
  Bottom 0.254: v70.58,148.86 v70.58,156.22
RF2_GPIO1  (via drill 0.5)
  Top 0.254: R86.2 19.62,159.18 v19.53,159.52
  Bottom 0.254: v19.53,159.52 19.53,144.03 17.24,141.74 6.32,141.74 3.96,139.38 | 3.96,139.38 3.78,139.2 | RF2_GPIO.2 3.96,139.38
RF2_GPIO2
  Top 0.254: RF2_GPIO.4 6.57,139.46 9.62,142.51 R85.1
RST
  Top 0.254: MSP430F47187.100 68.67,61.6 65.65,58.58 54.58,58.58 46.96,66.2 46.96,77.74 47.98,78.75 47.99,78.74 48.1,78.85 49.88,78.85 51.3,80.28
  Top 0.406: C13.2 55.85,78.75 55.76,78.84 R11.2 52.32,81.29 51.3,80.28 JTAG.11
  Bottom 0.254: JTAG.11 50.01,79.01 50.01,76.97 49.5,76.47 44.42,76.47 44.17,76.21 44.09,76.29 S3.2
S0
  Top 0.254: MSP430F47187.19 80.3,57.33 82.27,55.51 101.95,55.51 102.84,56.4 102.84,86.63 LCD1.P$14
S1
  Top 0.254: MSP430F47187.20 80.8,57.51 82.39,56.15 101.57,56.15 102.33,56.91 102.33,87.39 LCD1.P$13
S2
  Top 0.254: MSP430F47187.21 81.3,57.75 82.52,56.78 101.19,56.78 101.82,57.42 101.82,87.9 LCD1.P$12
S3
  Top 0.254: MSP430F47187.22 81.8,58.01 82.65,57.42 100.55,57.42 101.32,58.18 101.32,88.4 LCD1.P$11
S4
  Top 0.254: MSP430F47187.23 82.3,58.4 82.75,57.92 100.05,57.92 100.81,58.69 100.81,82.31 LCD1.P$10
S5
  Top 0.254: MSP430F47187.24 82.8,58.66 83.03,58.43 99.54,58.43 100.3,59.19 100.3,88.4 LCD1.P$9
S6
  Top 0.254: MSP430F47187.25 83.3,59.69 84.04,58.94 99.03,58.94 99.79,59.7 99.79,87.9 LCD1.P$8
S7
  Top 0.254: MSP430F47187.26 99.15,61.6 99.28,61.73 99.28,87.39 LCD1.P$7
S8
  Top 0.254: MSP430F47187.27 98.38,62.1 98.78,62.5 98.78,86.63 LCD1.P$6
S9
  Top 0.254: MSP430F47187.28 97.61,62.6 98.27,63.26 98.27,85.61 LCD1.P$5
S10
  Top 0.254: MSP430F47187.29 97.09,63.1 97.76,63.77 97.76,84.85 LCD1.P$4
S11
  Top 0.254: MSP430F47187.30 96.57,63.6 97.25,64.27 97.25,83.83 LCD1.P$3
S12
  Top 0.254: MSP430F47187.31 96.31,64.1 96.74,64.53 96.74,83.22 81.61,89.9 80.46,90.44 LCD1.P$2
S13
  Top 0.254: MSP430F47187.32 95.8,64.6 96.24,65.04 96.24,82.31 LCD1.P$1
S14  (via drill 0.5)
  Top 0.254: MSP430F47187.33 95.28,65.1 95.73,65.54 95.73,76.72 v94.74,77.84
  Bottom 0.254: v94.74,77.84 94.81,77.84 95.47,78.5 95.47,84.85 98.52,87.9 105.89,87.9 107.16,89.17 107.16,92.72 | 107.16,92.72 107.16,92.21 | 107.16,92.72 107.16,104.41 LCD1.P$19
S15  (via drill 0.6)
  Top 0.254: MSP430F47187.34 95.02,65.6 95.22,65.8 95.22,74.18 94.97,74.43 94.94,74.41 v94.76,74.41
  Bottom 0.254: v94.76,74.41 94.18,74.43 93.82,74.79 93.82,78.12 94.97,79.26 94.97,85.1 98.27,88.4 103.86,88.4 104.62,89.17 104.62,103.39 95.73,112.28 LCD1.P$20
S16  (via drill 0.5)
  Top 0.254: MSP430F47187.35 94.25,66.1 94.46,66.31 94.46,67.58 v94.33,67.7
  Bottom 0.254: 93.21,74.69 93.19,74.69 | 93.21,74.69 93.21,74.66 94.46,73.42 94.46,67.83 v94.33,67.7 | 93.21,74.69 93.21,78.27 94.46,79.51 94.46,85.36 98.01,88.91 101.32,88.91 102.08,89.67 102.08,104.41 LCD1.P$21
S17  (via drill 0.5)
  Top 0.254: MSP430F47187.36 92.23,66.6 93.06,67.42 v93.06,72.02
  Bottom 0.254: v93.06,72.02 93.06,73.04 92.17,73.93 92.17,78.75 93.44,80.02 93.44,85.86 97,89.42 97,104.15 92.43,108.72 92.43,111.77 90.9,113.3 LCD1.P$22
S18  (via drill 0.5)
  Top 0.254: v93.44,108.98 91.16,108.98 88.11,112.03 LCD1.P$23 | MSP430F47187.37 91.44,67.1 v91.92,67.83
  Bottom 0.254: v91.92,67.83 91.92,68.34 92.17,68.59 93.95,68.59 93.95,73.16 92.68,74.43 92.68,78.5 93.95,79.77 93.95,85.61 97.76,89.37 99.28,89.37 99.54,89.67 99.54,105.17 95.73,108.98 v93.44,108.98
S19
  Top 0.254: MSP430F47187.38 90.16,67.6 92.07,69.38 92.04,83.22 76.83,89.78 76.68,89.93 76.7,89.95 76.7,97.83 85.57,106.69 LCD1.P$24
S20
  Top 0.254: MSP430F47187.39 89.9,68.1 91.41,69.61 91.38,82.97 76.65,89.14 76.63,89.14 76.17,89.6 76.17,89.8 76.14,97.29 76.14,100.06 83.03,106.95 LCD1.P$25
S21
  Top 0.254: MSP430F47187.40 89.64,68.6 90.9,69.86 90.9,82.61 76.42,88.66 75.64,89.45 75.64,89.57 75.61,96.84 75.61,101.05 80.49,105.93 LCD1.P$26
SFD_A  (via drill 0.5)
  Top 0.254: v71.19,79.18 71.19,79.16 73.3,77.05 MSP430F47187.71 | v79.98,127.52 97.76,127.52 98.52,128.28 v98.52,128.43 | R69.2 96.59,155.56 v96.49,155.46
  Bottom 0.254: 72.36,88.66 | 72.36,88.66 72.36,88.73 72.36,102.37 72.36,102.63 77.44,107.96 77.44,114.31 79.22,116.09 79.22,126.76 v79.98,127.52 | 72.36,88.66 72.36,81.34 71.19,80.17 v71.19,79.18 | v98.52,128.43 98.52,153.43 v96.49,155.46
SFD_B  (via drill 0.5)
  Top 0.254: MSP430F47187.69 74.3,72.75 v74.57,72.48 | R80.2 34.69,155.13 v34.51,154.95
  Bottom 0.254: v74.57,72.48 73.38,73.93 68.8,73.93 66.01,76.72 66.01,88.66 67.03,89.67 67.03,103.26 69.31,105.57 69.31,142.25 57.63,154.44 35.02,154.44 v34.51,154.95
SW1  (via drill 0.5)
  Top 0.254: MSP430F47187.88 70.56,67.6 73.88,64.27 74.65,64.27 75.05,63.87 v75.05,63.77 | v123.67,112.03 122.91,112.79 122.91,134.35 123.29,134.73 124.07,134.73 124.18,134.63 124.23,134.68 R5.1 124.23,137.48 124.68,137.93 124.66,137.96 S1.1 126.49,137.96 128.24,139.71 131.8,139.71 137.38,145.3 137.38,158 127.22,168.16 127.22,168.67 111.98,168.67 | 111.98,168.67 112.49,168.67 | 111.98,168.67 16.99,168.67 5.3,159.27 5.3,138.19 4.03,136.92 RF2_GPIO.1
  Bottom 0.254: v123.67,112.03 123.41,112.03 122.91,111.52 122.91,107.96 116.56,101.61 116.56,88.4 111.48,83.32 111.48,58.69 110.71,57.92 105.38,57.92 101.32,61.99 87.09,61.99 86.11,62.97 75.7,62.97 75.05,63.61 v75.05,63.77 75.15,63.77
SW2
  Top 0.254: 124.33,121.35 124.28,121.3 124.24,121.34 R6.1 124.18,120.15 124.61,119.72 S2.1 124.61,117.28 | 129.51,107.71 SW2_JMP.2 124.43,112.79 124.43,117.11 124.61,117.28 | 124.61,117.28 124.68,117.36
TA0  (via drill 0.5)
  Top 0.254: MSP430F47187.91 67.74,66.1 65.76,68.08 65.76,100.34 68.55,103.14 68.55,114.57 66.26,116.09 60.68,116.09 v60.42,115.84
  Bottom 0.254: v60.42,115.84 60.42,115.07 59.91,114.57 51.02,114.57 50.26,113.8 42.51,113.8 41.56,114.76 | 41.56,114.76 41.52,114.8 | 41.56,114.76 41.63,114.82 41.55,114.9 HDR0.1
TA0I
  Top 0.254: MSP430F47187.90 68.01,66.6 66.26,68.34 66.26,100.09 69.06,102.88 69.06,115.07 66.52,116.85 50.01,116.85 48.23,118.63 45.69,118.63 44.09,117.03 HDR0.2
TA1
  Top 0.254: MSP430F47187.89 68.32,67.1 67.86,67.55 66.75,68.57 66.75,99.81 69.57,102.63 69.57,115.33 66.77,117.61 52.8,117.61 52.29,118.12 52.29,120.92 51.28,121.93 JP7.3
TB0  (via drill 0.5)
  Top 0.254: MSP430F47187.70 73.8,72.82 v73.38,72.5 | v49.25,89.93 49.25,92.72 v49.75,93.23 | v60.42,83.07 60.68,83.07 v62.2,81.55 | v37.05,115.58 39.59,115.58 40.61,114.57 44.42,114.57 46.71,116.85 HDR0.3
  Bottom 0.254: 62.45,75.96 62.45,75.91 | 62.45,75.96 62.45,81.29 v62.2,81.55 | 62.45,75.96 62.45,71.13 62.71,70.88 71.85,70.88 73.32,72.35 v73.38,72.5 | v60.42,83.07 60.42,83.83 58.9,85.36 52.55,85.36 49.25,88.66 v49.25,89.93 | v49.75,93.23 49.75,95.52 48.48,96.79 39.85,96.79 38.83,97.8 38.83,107.2 36.04,109.99 36.04,114.57 v37.05,115.58
TCK
  Top 0.254: MSP430F47187.99 68.35,62.1 65.48,59.22 54.81,59.22 47.47,66.56 47.47,73.11 48.41,74.05 50.08,74.05 51.28,75.25 | 51.28,75.25 51.3,75.27 | 51.28,75.25 JTAG.7
TDI
  Top 0.254: 67.79,63 65.04,60.26 56.84,60.26 50.24,66.84 50.24,69.13 51.23,70.12 JTAG.3 | 67.79,63 67.81,63.03 | MSP430F47187.97 67.88,63.1 67.79,63
TDO
  Top 0.254: MSP430F47187.96 67.64,63.6 64.89,60.85 58.06,60.85 51.33,67.58 JTAG.1 51.28,67.53
TEMP_1
  Top 0.406: C50.1 32.23,63.51 32.74,64.02 32.74,65.29 32.72,65.31 IS02.2 32.72,66.35 33.41,67.05 33.41,67.74 33.5,67.83 33.41,67.92 R122.1 | D26.A 18.51,64.02 19.02,64.53 19.02,65.8 D11.A
  Top 0.61: 19.02,64.53 19.02,66.31 20.04,67.32 25.62,67.32 27.66,65.29 27.66,63.51 C50.1
TMS  (via drill 0.5)
  Top 0.254: 68.03,62.51 65.27,59.75 55.77,59.75 55.77,59.78 v51.53,64.02 | 68.03,62.51 68.07,62.55 | 68.03,62.51 68.04,62.5 68.14,62.6 MSP430F47187.98
  Bottom 0.254: v51.53,64.02 50.01,65.54 50.01,71.64 51.02,72.66 JTAG.5
UART_RX  (via drill 0.5)
  Top 0.254: R47.2 110.7,74.93 111.09,75.32 | 110.46,74.94 110.47,74.93 R47.2 | R47.2 110.56,74.84 110.71,74.69 JP12.4 | 104.87,82.31 JP12.1
  Top 0.406: 111.09,75.32 U3.6 | 104.87,82.31 103.86,81.29 103.86,76.97 JP12.4 | JP12.1 106.14,83.83 107.41,85.1 v120.87,85.1
  Bottom 0.406: 135.1,112.28 J2.1 135.35,112.03 131.29,107.96 131.29,90.44 125.95,85.1 v120.87,85.1
UART_TX  (via drill 0.5)
  Top 0.254: 106.34,67.37 JP13.4 105.13,67.32
  Top 0.406: 106.34,67.37 R52.1 | 105.13,67.32 104.36,66.56 104.36,61.73 JP13.1 109.95,56.4 116.81,56.4 118.59,54.11 v120.62,54.11
  Bottom 0.406: J1.1 135.35,104.91 139.16,101.1 139.16,56.91 136.37,54.11 v120.62,54.11
V1+
  Top 0.254: 43.91,51.57 43.9,51.56 C15.1 43.86,51.37 43.66,51.57 43.91,51.83 | MSP430F47187.1 71.3,59.66 68.55,56.91
  Top 0.406: 40,48.76 39.92,48.83 | C14.1 40,48.76 | 40,48.76 C14.1 R15.1 43.99,51.12 43.9,51.21 C15.1 | 43.91,51.83 43.91,52.84 48.23,56.91 68.55,56.91
V1-  (via drill 0.5)
  Top 0.254: 45.49,51.37 45.44,51.32 | C15.2 45.49,51.37 | 45.49,51.37 45.59,51.47 | MSP430F47187.2 71.8,58.89 68.8,55.89
  Top 0.406: 36.29,41.19 36.37,41.11 C16.1 | C16.1 36.48,40.99 36.55,40.93 36.38,40.77 | 45.69,51.32 45.64,51.37 C15.2 | v45.69,41.16 45.69,51.32 | 45.69,51.32 45.69,52.34 49.25,55.89 68.8,55.89 | v41.37,40.65 41.37,42.43 41.12,42.68 37.05,42.68 36.55,42.18 36.55,41.16 | C16.1 36.48,40.97 36.55,40.91 36.55,41.16 | 36.55,41.16 36.49,41.11 C16.1 | 36.55,41.16 36.55,37.1 35.28,35.83 34.26,35.83 34.01,35.57 33.92,35.66 R18.1
  Bottom 0.406: v41.37,40.65 45.18,40.65 v45.69,41.16
V2+
  Top 0.254: MSP430F47187.3 72.3,58.62 66.26,52.59 | 62.96,52.59 62.9,52.65 C18.1
  Top 0.406: C18.1 62.52,52.65 62.45,52.59 62.42,52.63 R22.1 57.66,52.63 57.63,52.59 57.6,52.62 C17.1 | 62.96,52.59 66.26,52.59
V2-  (via drill 0.5)
  Top 0.254: 62.73,51.04 62.83,50.94 | MSP430F47187.4 72.8,58.36 65.25,50.81 | 62.96,50.81 62.82,50.95 C18.2
  Top 0.406: R25.1 52.86,45.29 53.09,45.52 C19.1 53.09,46.28 v54.33,47.51 | C18.2 62.73,51.04 62.71,51.07 v62.71,48.53 | 62.96,50.81 65.25,50.81
  Bottom 0.406: v54.33,47.51 61.69,47.51 v62.71,48.53
V3+
  Top 0.254: 71.34,51.32 71.41,51.26 C35.1 | 71.34,51.57 71.41,51.51 C35.1 | MSP430F47187.5 73.3,58.1 70.33,55.13 70.33,51.32 70.58,51.07 71.34,51.07 C35.1
  Top 0.406: C35.1 71.41,50.88 71.34,50.81 R57.1 68.46,48.61 68.42,48.65 | 68.42,48.65 68.3,48.78 | C33.1 68.42,48.65
V3-  (via drill 0.5)
  Top 0.254: 73.12,51.07 73.2,51.14 | 73.12,51.57 72.87,51.32 73.07,51.12 C35.2 73.11,51.31 73.22,51.42 73.22,54.62 73.8,55.2 MSP430F47187.6
  Top 0.406: R58.1 66.61,40.74 66.77,40.91 66.76,40.92 C34.1 66.76,41.66 68.04,42.94 v69.57,42.94 | C35.2 73.11,51.08 73.12,51.07 v73.12,43.95
  Bottom 0.406: v69.57,42.94 72.11,42.94 v73.12,43.95
VCC5  (via drill 0.7)
  Top 0.406: U$9.6 42.61,133.59 41.88,132.85 36.04,132.85 35.78,133.11 | U$8.6 35.75,134.15 35.78,134.12 35.78,133.11 | 35.78,133.11 34.51,133.11 v34.01,132.6
  Top 0.61: U$5.3 24.58,130.04 24.1,129.55 5VDC.3 5VDC.2 5VDC.1
  Bottom 0.61: U$5.3 31.24,130.04 32.48,128.79 | 32.48,128.79 32.48,104.66 31.21,103.39 19.53,103.39 17.24,104.91 U$6.5 | 32.48,128.79 32.48,131.08 v34.01,132.6
VCC12  (via drill 0.6)
  Top 0.61: U$14.7 51.2,98.48 v50.52,97.8 | U$4.12V 30.06,119.02 34.77,114.31 39.09,114.31 41.12,112.28 C29.+ | U$5.1 16.96,137.15 13.94,134.12 10.38,134.12 9.88,133.62 12VDC.3 12VDC.2 12VDC.1
  Bottom 0.61: v50.52,97.8 41.88,97.8 39.85,99.83 39.85,110.76 41.12,112.03 C29.+ 40.61,112.28 38.83,114.06 38.83,130.82 | 38.83,130.82 38.83,132.09 33.78,137.15 U$5.1 26.87,137.15 | U$7.1 37.54,129.53 38.83,130.82 | 26.87,137.15 26.64,136.92 | C28.+ 28.16,138.44 26.87,137.15
VREF  (via drill 0.7)
  Top 0.254: v81,49.54 81,49.8 75.3,55.49 MSP430F47187.9
  Top 0.406: C1.2 81.43,49.97 v81,49.54
  Bottom 0.406: 49.09,46.85 JP2.3 49.09,46.9
  Bottom 0.61: v81,49.54 93.19,49.54
  Bottom 0.813: 105.63,49.54 104.87,50.3 93.95,50.3 93.19,49.54 JP3.3 | 105.63,49.54 JP4.3 | 105.63,49.54 106.4,50.3 118.59,50.3 119.35,49.54 | 119.35,49.54 JP10.3 | 119.35,49.54 120.11,50.3 132.3,50.3 133.07,49.54 JP11.3 | JP1.3 44.65,42.41 49.09,46.85 | 49.09,46.9 55.7,40.3 JP9.3 67.38,40.3 69.06,38.62 71.6,38.62 79.47,46.49 79.47,48.27 80.74,49.54 v81,49.54
VREG_EN_A  (via drill 0.5)
  Top 0.254: 83.98,72.6 MSP430F47187.48 | 83.98,72.6 83.98,72.57 | v83.28,71.75 83.98,72.6 | 116,149.16 115.79,149.36 R61.1 116.01,149.15 116.05,149.11 116.05,148.09 115.03,147.08 v111.98,147.08 | v110.46,132.09 v85.06,132.09
  Bottom 0.254: 78.46,111.52 78.43,111.52 | v83.28,71.75 83.28,75.7 81.5,77.48 81.5,81.8 80.23,83.07 80.23,87.39 79,88.62 78.96,94.11 80.23,95.38 80.23,109.49 78.46,111.26 78.46,111.52 | 78.46,111.52 78.46,113.8 80.23,115.58 80.23,124.73 85.57,130.06 85.57,131.58 v85.06,132.09 | v110.46,132.09 110.46,145.55 v111.98,147.08
VREG_EN_B  (via drill 0.5)
  Top 0.254: MSP430F47187.87 71.08,68.1 74.14,65.04 76.17,65.04 v76.68,64.53 | v82.27,63.89 82.27,67.07 83.03,67.83 83.03,70.12 82.01,71.13 81.96,71.08 v81.88,71.08 | SW2_JMP.1 130.53,105.42 131.54,106.44 131.54,109.49 128.24,112.79 128.24,124.98 v124.29,128.8 | R108.1 65.43,149.69 v65.5,149.62 | v65.5,167.17 v65.5,163.59
  Bottom 0.254: v81.88,71.08 81.88,71.36 81.87,71.37 82.77,72.52 82.77,73.67 81.5,74.94 69.31,74.94 67.03,77.23 67.03,88.15 68.07,89.19 68.04,102.3 68.02,102.78 70.4,105.3 70.33,144.79 v65.5,149.62 v65.5,163.59 | v124.29,128.8 123.91,128.8 120.37,132.35 120.37,152.41 119.6,153.17 110.46,153.17 96.74,166.89 66.01,166.89 v65.5,167.17 | v76.68,64.53 76.68,64.27 77.07,63.89 v82.27,63.89
WATT_RX
  Top 0.406: U$9.4 30.64,137.11 29.43,135.9 29.43,128.28 24.61,123.46 U$6.11
WATT_TX
  Top 0.406: U$8.4 31.65,136.09 30.96,135.39 30.96,127.77 27.4,124.22 U$6.10
XIN
  Top 0.254: 75.79,79.41 75.76,79.39 75.73,79.42 XT1.P2 75.67,79.27 75.66,79.26 75.69,79.24 75.69,77.79 76.3,77.18 MSP430F47187.65
  Top 0.61: C6.1 76.88,79.72 76.58,79.41 75.79,79.41
XOUT
  Top 0.254: 73.05,79.44 73.07,79.41 73.07,79.42 XT1.P1 73.17,79.31 73.12,79.26 75.8,76.58 MSP430F47187.66
  Top 0.61: C7.2 72.07,79.73 72.36,79.44 73.05,79.44
XT2IN
  Top 0.254: MSP430F47187.94 67.06,64.6 65.68,65.98 63.06,65.98 | C10.2 61.35,66.01 59.23,63.89
  Top 0.406: 63.06,65.98 63.03,66.01 C10.2 | XT2.1 59.23,63.89
XT2OUT
  Top 0.254: 63.37,69.68 64.23,69.68 64.66,69.25 64.66,67.7 67.27,65.1 MSP430F47187.93 | 59.18,68.87 59.15,68.85 | XT2.3 59.18,68.87 | C12.2 60.13,69.82 59.18,68.87
  Top 0.406: 63.39,69.79 63.36,69.82 C12.2 63.23,69.82 63.37,69.68
ZAOUT  (via drill 0.5)
  Top 0.406: ISO1.3 34.79,50.54 Z1.1 33.92,51.41 R32.2 33.92,54.28 34.01,54.37 32.48,54.37 30.96,55.89 v30.96,57.92 | v31.72,67.83 v31.72,70.62 | U$10.P$2 9.73,96.9 v9.37,96.53
  Bottom 0.406: v30.96,57.92 30.96,60.72 31.72,61.48 v31.72,67.83 | v31.72,70.62 31.72,86.88 33.24,88.4 33.24,94.25 38.07,99.07 38.07,101.1 36.55,102.63 27.4,102.63 26.64,101.87 9.88,101.87 8.86,100.85 8.86,97.29 9.37,96.79 v9.37,96.53
ZBOUT  (via drill 0.5)
  Top 0.254: U$10.P$5 12.22,94.95 12.67,94.5 v12.67,92.72 | v15.21,83.07 28.42,83.07 29.43,84.09 41.63,84.09 45.44,80.28 45.44,58.94 41.88,55.38 Z2.1
  Top 0.406: R39.2 39.68,53.44 Z2.1 38.58,58.43 33.24,58.43 32.72,57.9 IS02.3
  Bottom 0.254: v12.67,92.72 12.67,86.37 15.21,83.83 v15.21,83.07
ZC  (via drill 0.5)
  Top 0.254: 20.27,95.79 20.29,95.77 20.12,95.6 U$10.P$11
  Top 0.406: 20.27,95.79 ZXING.1 | U$14.10 60.75,99.76 v61.18,99.33 | 20.29,95.77 20.29,98.06 19.53,98.82 17.5,98.82 15.97,100.34 15.97,103.39 16.48,103.9 41.63,103.9 v42.13,103.39
  Bottom 0.406: v61.18,99.33 61.18,102.88 60.68,103.39 v42.13,103.39
ZCA
  Top 0.254: U$10.P$13 14.93,96.9 14.28,96.25 11.68,96.25 11.65,96.28 11.62,96.25 U$10.P$3
ZCB  (via drill 0.5)
  Top 0.254: 741G57.1 21.07,78.01 20.29,77.23 16.99,77.23 v15.21,78.75 | U$10.P$6 10.69,94.3 10.13,93.74 v10.13,92.72
  Bottom 0.254: v10.13,92.72 10.13,91.96 10.64,91.45 10.64,85.61 15.21,81.04 v15.21,78.75
ZCC  (via drill 0.5)
  Top 0.254: 741G57.6 17.56,78.82 v17.24,78.5 | v18.26,89.93 18.26,91.92 17.28,92.9 17.28,93.55 17.31,93.58 U$10.P$8
  Bottom 0.254: v17.24,78.5 16.73,78.5 16.13,79.03 16.12,86.48 16.12,87.28 18.26,89.42 v18.26,89.93
ZCOUT  (via drill 0.5)
  Top 0.254: U$10.P$10 18.32,94.95 v20.54,92.72 | 28.42,82.05 27.91,82.56 23.59,82.56 v23.08,82.05
  Top 0.406: ISO3.3 40.53,80.71 41.37,81.55 | 28.42,80.78 R42.2 | 28.42,80.78 28.49,80.86 | 28.42,80.78 28.42,82.05 29.18,82.82 40.1,82.82 41.37,81.55 | 41.37,81.55 41.4,81.52 Z3.1
  Bottom 0.254: v23.08,82.05 23.08,90.18 v20.54,92.72

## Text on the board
tNames: Smart Meter Board Ver 2.5 | Texas Instruments Inc. | + | + | BZ3 | BZ2 | + | BZ1 | 1 | 51 | + | 76 | + | 8 | 1 | IT3 | 8 | 1 | C10 | + | 26 | 1 | + | IT2 | + | IT1 | Feb 2010 | V1- | V1+ | V2- | V2+ | V3- | V3+ | I1- | I1+ | I2- | I2+ | I3- | I3+ | IN- | IN+ | K.Venkat
_tplace: Smart Meter Board Ver 2.5 | Texas Instruments Inc. | R73 | EZRF | R84 | R86 | R75 | R72 | R83 | TP26 | TP10 | EZRF_EN | R82 | TP27 | R71 | R76 | TP13 | R85 | R74 | R70 | R81 | TP25 | TP4 | 2 | 4 | R87 | TP24 | R107 | R69 | TP8 | + | R80 | C43 | R68 | R60 | 1 | 3 | C44 | R106 | + | C45 | R79 | R67 | R30 | R105 | R40 | 3 | R78 | C42 | R66 | R27 | TP23 | R108 | R10 | R41 | 1 | R77 | 1 | 1 | 1 | R61 | RF1_FIFO | 2 | 2 | 4 | 2 | 4 | RF4 | TP22 | RF2 | TP21 | 1 | 3 | 1 | C28 | RF3 | 3 | 3_3VDC | TP20 | RF1 | 1 | RF2_GPIO | WMBUS_UART0 | S1 | 2 | 4 | 4 | 2.4RF_UART | 1 | 3 | 3 | R8 | U$9 | 1 | 2 | 4 | R5 | 3 | 3 | U$8 | 1 | S4 | 2 | 1 | 3 | DGND | 2 | 5VDC | 2 | 4 | 2 | 2 | 4 | 1 | RF2_FIFO | 3 | GND | 1 | 1 | 1 | 5 | 1 | 12VDC | 2 | 4 | RF1_GPIO | 1 | 3 | 1 | 2 | 3 | WMBUS_UART1 | 4 | 2 | R9 | 1 | 1 | 3 | LED_EN | LED1 | 3 | 2 | 1 | 2 | 3 | 4 | R1 | OK2 | SL2 | R6 | 18 | 10 | 2 | 4 | R2 | DVCC | 2 | 3 | JP7 | 1 | 3 | R3 | 1 | 1 | PLC_UART | LED2 | HDR0 | 34 | 3 | 4 | LED3 | 1 | 2 | 3 | 33 | R89 | S2 | J2 | R109 | SW2_JMP | R46 | C29 | J1 | 1 | 9 | JP6 | 4 | 2 | R49 | R37 | R36 | R38 | ZXING | 1 | 3 | SL1 | 1 | PLC_GPIO | 1 | 14 | Q9 | Q10 | BZ3 | 1 | 2 | R35 | Q11 | Q5 | Q8 | R34 | PLCGND | OK1 | R126 | C26 | C9 | RS-232 | R43 | -L1 | -L2 | R88 | 741G57 | C6 | C8 | JP5 | R48 | Q4 | R33 | Z3 | R11 | J3 | C57 | PLCV2 | BZ2 | C7 | 1 | R42 | D9 | + | 2 | 4 | 3 | U3 | BZ1 | 741G57 | C13 | C11 | 3 | D14 | 5 | 4 | 5 | 1 | C53 | XT1 | 51 | + | C4 | JP12 | R47 | 9 | 3 | 6 | Q6 | R124 | 14 | 76 | 4 | 4 | 1 | 2 | + | 8 | D27 | R123 | S3 | C2 | 8 | 1 | R45 | 2 | 7 | Q3 | 3 | 3 | U4 | 7 | 1 | 8 | R118 | R52 | 2 | R51 | 2 | C12 | 4 | 6 | R117 | R116 | 1 | IT3 | R122 | 1 | XT2 | 4 | 5 | D11 | C50 | 2 | 1 | PWR_JMP | 2 | 1 | 3 | R50 | 8 | 1 | C10 | 3 | 6 | D26 | C10 | JP13 | 2 | + | Q2 | R121 | JTAG | J5 | 26 | C31 | 2 | 7 | 1 | D15 | 3 | 4 | 1 | MSP430F47187 | C32 | 1 | 8 | D16 | R115 | Z2 | C17 | + | R114 | R113 | PLCV3 | R39 | C15 | C18 | C3 | IT2 | R120 | 1 | 4 | R32 | R22 | + | 4 | 5 | 1 | C35 | C5 | C14 | C1 | 2 | 3 | R15 | 2 | C33 | JP3 | JP4 | JP10 | JP11 | 3 | 6 | Z1 | R23 | R57 | Q1 | C30 | 1 | 2 | 7 | JP1 | R16 | 3 | R56 | R7 | D25 | R14 | R21 | 1 | C40 | C41 | R119 | 2 | 1 | 2 | 3 | 1 | 2 | 3 | 1 | 2 | 3 | 1 | 2 | 3 | 1 | 8 | C16 | C19 | C21 | C24 | R101 | 3 | JP2 | 2 | C34 | R55 | R25 | R19 | R20 | C37 | C39 | 3 | R54 | R104 | IT1 | D10 | R13 | R24 | C25 | R102 | R103 | R58 | C23 | C36 | PLCV1 | JP9 | D5 | D19 | D17 | D23 | D21 | R18 | R4 | R112 | R111 | R110 | R12 | C22 | D7 | C38 | D3 | D1 | C20 | D20 | R63 | R17 | R59 | D6 | D18 | D24 | D22 | R28 | D4 | D2 | R26 | R31 | D8 | R29 | R65 | R62 | L15 | L6 | R64 | L3 | L5 | L12 | L8 | L14 | L17 | L2 | L1 | L4 | TVS1 | TVS2 | L7 | L16 | TVS3 | TVS4 | C58 | L13 | Feb 2010 | C60 | C59 | 1 | 2 | X1 | 1 | 2 | X2 | 1 | 2 | X3 | 1 | 2 | X4 | 1 | 2 | X5 | 1 | 2 | X6 | 1 | 2 | X7 | V1- | V1+ | V2- | V2+ | V3- | V3+ | I1- | I1+ | I2- | I2+ | I3- | I3+ | IN- | IN+ | K.Venkat
_bplace: 5 | 1 | 2 | 4 | 3 | 12V | GND | N | L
